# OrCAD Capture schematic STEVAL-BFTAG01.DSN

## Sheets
1 LOGHI
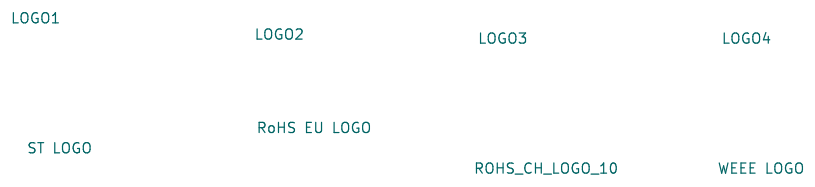
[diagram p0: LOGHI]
2 TOP_sch: size A
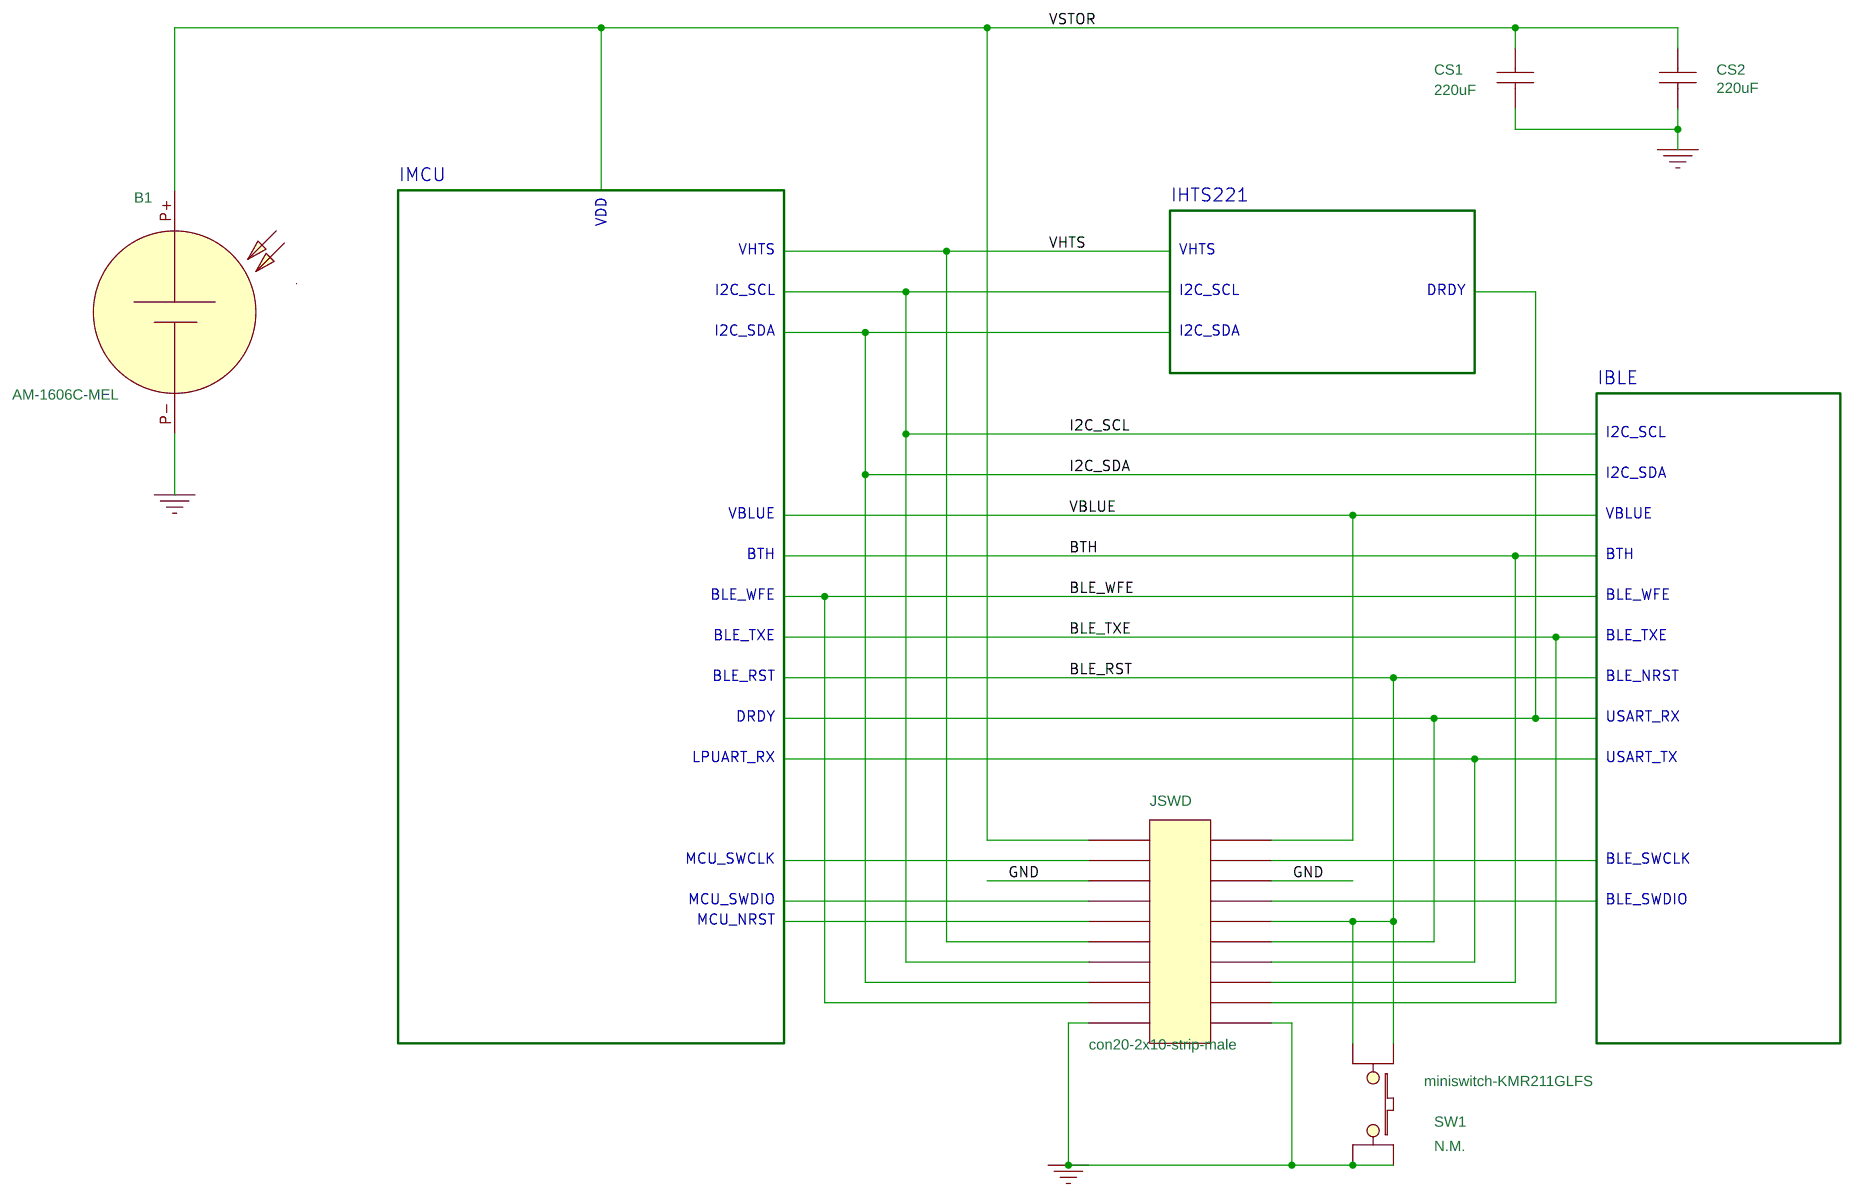
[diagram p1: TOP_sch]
3 MCU_sch: size A; block IMCU
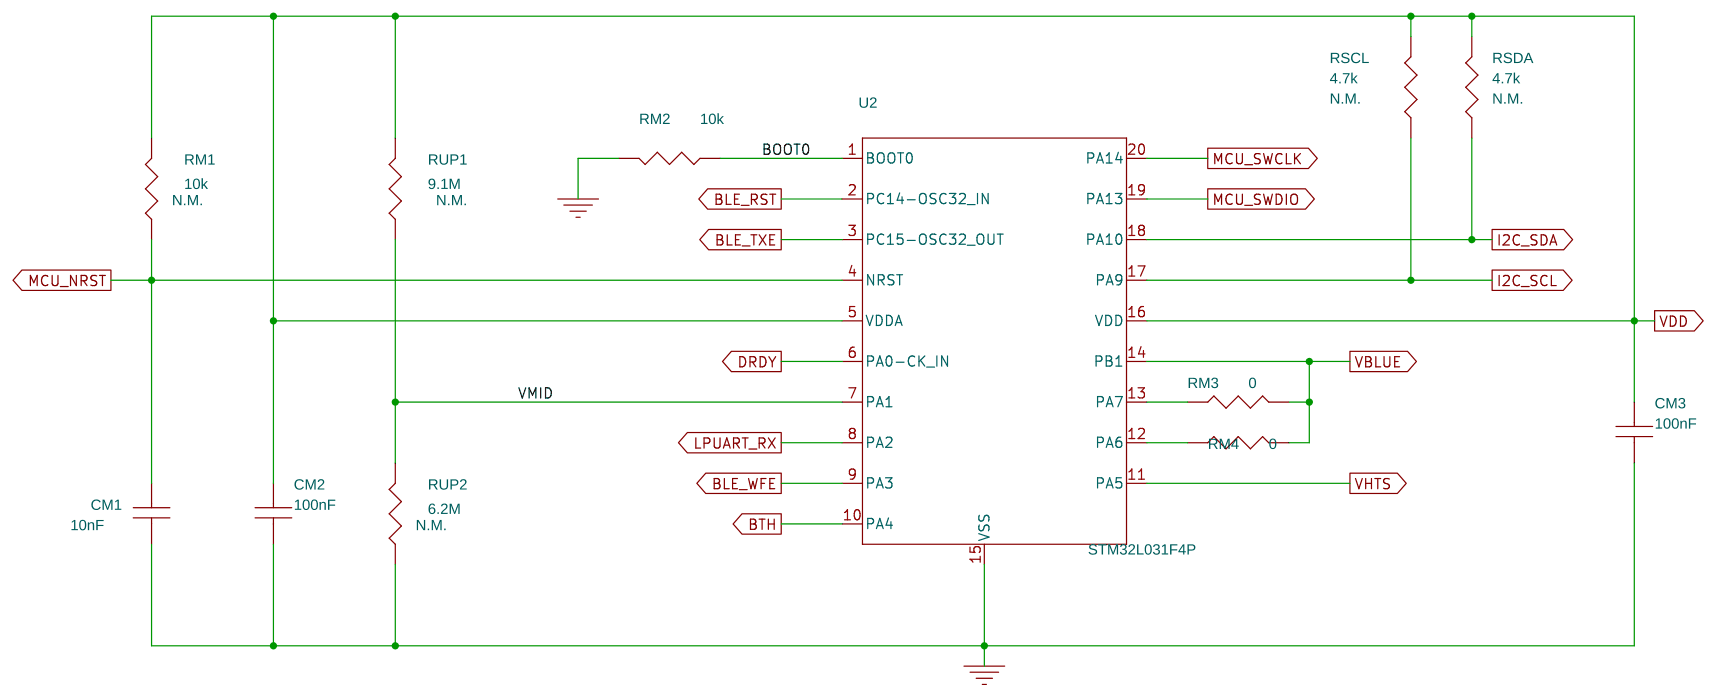
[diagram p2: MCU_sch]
4 BLE_sch: size A; block IBLE
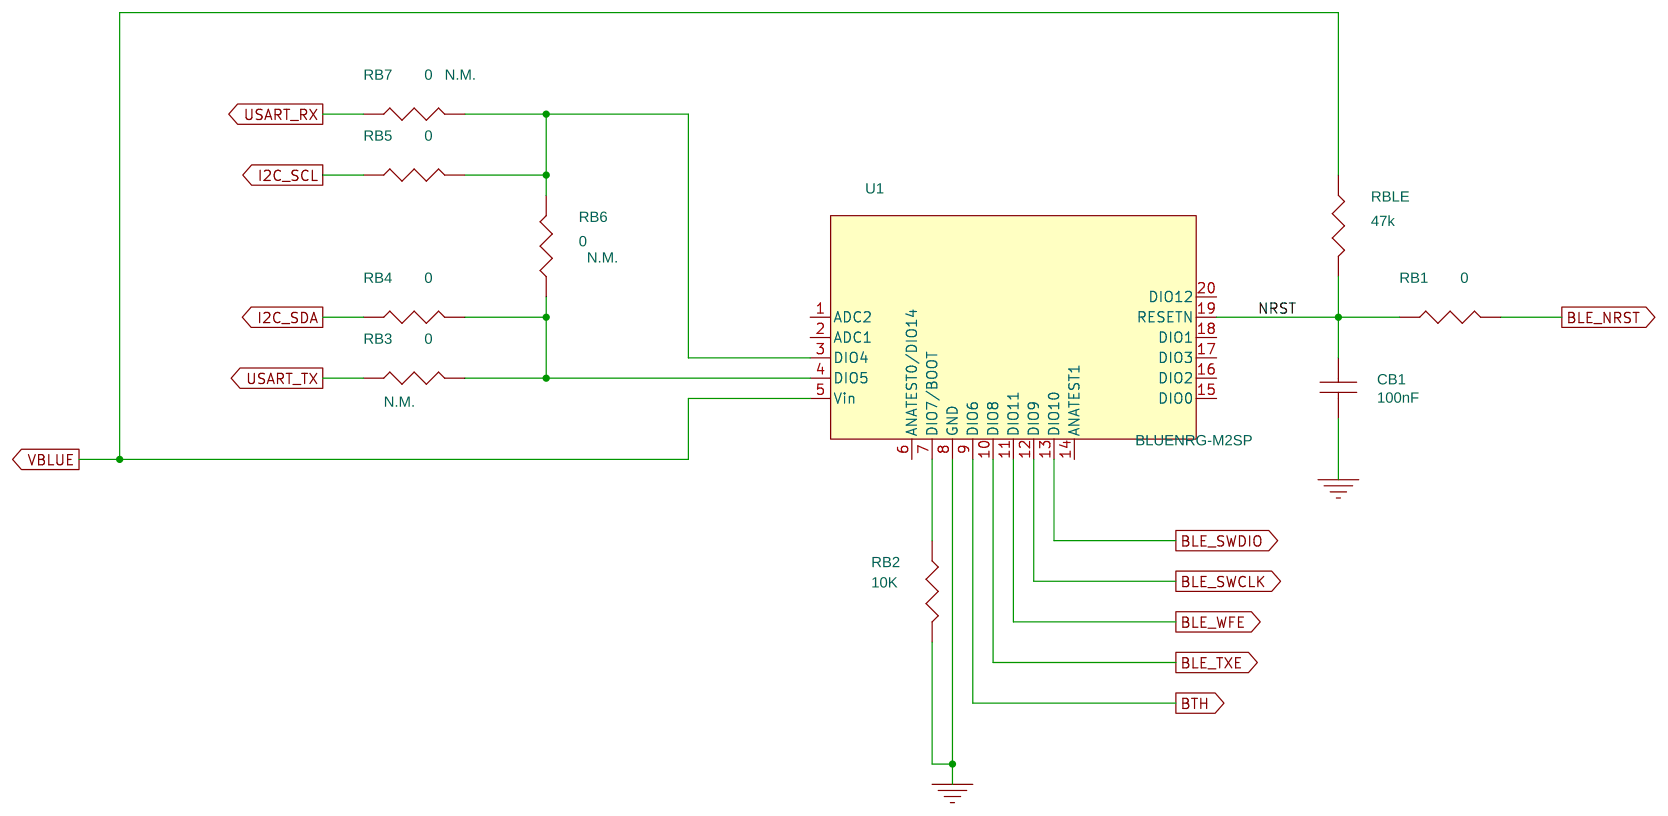
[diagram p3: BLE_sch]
5 HTS221_sch: size A; block IHTS221
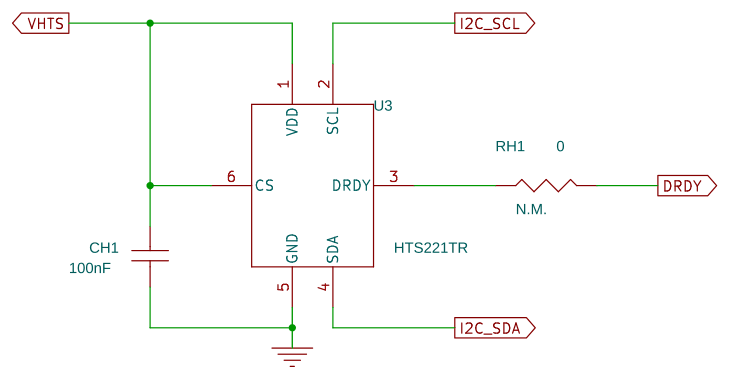
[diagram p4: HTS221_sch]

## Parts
sheet BLE_sch
CB1  100nF  [C_0402]
RB1  0  [r_0402]
RB2  10K  [r_0402]
RB3  0  [r_0402]
RB4  0  [r_0402]
RB5  0  [r_0402]
RB6  0  [r_0402]
RB7  0  [r_0402]
RBLE  47k  [r_0402]
U1  BLUENRG-M2SP  [BLUENRG-M2SP]
sheet HTS221_sch
CH1  100nF  [C_0402]
RH1  0  [r_0402]
U3  HTS221TR  [PQFN100P200X200X100-6N]
sheet LOGHI
LOGO1  ST LOGO  [STLogo12mm]
LOGO2  RoHS EU LOGO  [rohs-eu-logo13mm]
LOGO3  ROHS_CH_LOGO_10  [rohs-ch-10-12mm]
LOGO4  WEEE LOGO  [weee12mm]
sheet MCU_sch
CM1  10nF  [C_0402]
CM2  100nF  [C_0402]
CM3  100nF  [C_0402]
RM1  10k  [r_0402]
RM2  10k  [r_0402]
RM3  0  [r_0402]
RM4  0  [r_0402]
RSCL  4.7k  [r_0402]
RSDA  4.7k  [r_0402]
RUP1  9.1M  [r_0402]
RUP2  6.2M  [r_0402]
U2  STM32L031F4P  [sop20p65_650x640x120l60x24n]
sheet TOP_sch
B1  AM-1606C-MEL  [solar_panel_AM-1606C-MEL]
CS1  220uF  [C_1206_hd]
CS2  220uF  [C_1206_hd]
JSWD  con20-2x10-strip-male  [hdrv20w64p254_10x2_2540x508h838]
SW1  miniswitch-KMR211GLFS  [switch_SMT_4_2x2_8mm]

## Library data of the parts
CB1 CH1 CM1-CM3 = CAP: CAPACITOR CERAMIC SMD 0402; ALT_SYMBOLS: c_0402_hd; Any Equivalent?: YES; CLASS: DISCRETE; Dielectric Type: Capacitors; Manufacturer: ANY; Manufacturer PN: ANY; PART_NUMBER: CAP-00000065; Package Size: 0402 (1005 Metric); Rated Voltage: 10V; Tolerance: ±10%
RB1 RB2 RB4 RB5 RBLE RM2-RM4 = RES: CHIP RESISTOR SMD 5% 1/16W 0402; ALT_SYMBOLS: r_0402_hd; Any Equivalent?: YES; CLASS: DISCRETE; PART_NUMBER: RES-00000105; Package Size: 0402 (1005 Metric); Rated Power: 0.063W, 1/16W; Tolerance: 5%
RB3 RB6 RB7 RH1 RM1 RSCL RSDA RUP1 RUP2 = RES: CHIP RESISTOR SMD 5% 1/16W 0402; ALT_SYMBOLS: r_0402_hd; Any Equivalent?: YES; Assembly Information: N.M.; CLASS: DISCRETE; PART_NUMBER: RES-00000105; Package Size: 0402 (1005 Metric); Rated Power: 0.063W, 1/16W; Tolerance: 5%
U1 = BLUENRG-M2SP: RX TXRX MODULE BT PCB TRC SMD; Any Equivalent?: NO; CLASS: IC; Manufacturer: STMicroelectronics; PART_NUMBER: IC-00000068; Package Size: 20-SMD Module; Rated Power: 7dbm; Supply Voltage: 1.7V ~ 3.6V
U3 = HTS221_0: SENS HUMI/TEMP 2.5V I2C 4.5% SMD; Any Equivalent?: NO; Assembly Information: <Assembly Information>; CLASS: IC; Manufacturer: STMicroelectronics; PART_NUMBER: IC-00000088; Package Size: HLGA_6L2X2X09; Supply Voltage: 1.7 V ~ 3.6 V
LOGO1 = LOGO_ST: ST LOGO - SILKSCREEN; ALT_SYMBOLS: stlogo11mm,STLogo10mm,STLogo9mm,STLogo8mm,STLogo7mm,STLogo6mm,STLogo5mm,stlogo4mm; CLASS: Mechanical; PART_NUMBER: MECH-00000001
LOGO2 = RoHS_EU: RoHS EU - SILKSCREEN; ALT_SYMBOLS: rohs-eu-logo9mm,RoHS-Eu-Logo7mm,RoHS-Eu-Logo5mm; Any Equivalent?: NOT; CLASS: Mechanical; PART_NUMBER: MIS-00000007
LOGO3 = RoHS_CH_10: ROHS CHINA LOGO 10 - SILKSCREEN; ALT_SYMBOLS: rohs-ch-10-10mm,rohs-ch-10-8mm,rohs-ch-10-6mm,rohs-ch-10-5mm,rohs-ch-10-4mm; CLASS: Mechanical; PART_NUMBER: MIS-00000002
LOGO4 = WEEE: WEEE LOGO - SILKSCREEN; ALT_SYMBOLS: weee10mm,weee8mm,weee7mm; CLASS: Mechanical; PART_NUMBER: LOGO-00000001
U2 = STM32L031F4P: IC MCU 32BIT 16KB FLASH 20TSSOP; Any Equivalent?: NO; CLASS: IC; Manufacturer: STMicroelectronics; Manufacturer PN: STM32L031F4P3; PART_NUMBER: IC-00000115; Package Size: 20-TSSOP (0.173", 4.40mm Width); Supply Voltage: 1.8V ~ 3.6V
B1 = SOLAR_PANEL: Solar Panels & Solar Cells Solar BLE Sensor 15x15mm Min 100 Lux; Any Equivalent?: NO; CLASS: DISCRETE; Manufacturer: Panasonic Battery; PART_NUMBER: MIS-00000033
CS1 CS2 = CAP: CAP CER 220UF 4V X6S 1206; Any Equivalent?: NO; CLASS: DISCRETE; Manufacturer: Murata Electronics; Manufacturer PN: GRM31CC80G227ME11L; PART_NUMBER: CAP-00000262; Package Size: 1206 (3216 Metric); Rated Voltage: 4V; Temperature Coefficient: X6S; Tolerance: 20%
JSWD = CON20A: CONN HEADER .100 DUAL STR 20POS; CLASS: IO; PART_NUMBER: CON-00000033
SW1 = PUSHBUTTON-SPST-2: SWITCH TACTILE SPST-NO 0.05A 32V; Assembly Information: N.M.; CLASS: DISCRETE; Manufacturer: C&K; Manufacturer PN: KMR211GLFS; PART_NUMBER: TMP-285; Package Size: 4.60mm x 2.80mm

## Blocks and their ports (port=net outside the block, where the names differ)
IMCU = schematic MCU, on sheet TOP_sch: BLE_RST, VBLUE, MCU_SWCLK=N16953, MCU_SWDIO=N02299, MCU_NRST=N16984, VDD=VSTOR, BLE_WFE, VHTS, BTH, BLE_TXE, I2C_SCL, I2C_SDA, DRDY=N18720, LPUART_RX=N18701
IHTS221 = schematic SENSORS, on sheet TOP_sch: I2C_SDA, DRDY=N18720, VHTS, I2C_SCL
IBLE = schematic BLE, on sheet TOP_sch: VBLUE, BLE_SWDIO=N01742, BLE_SWCLK=N01725, BLE_NRST=BLE_RST, BLE_WFE, BTH, USART_RX=N18720, BLE_TXE, USART_TX=N18701, I2C_SCL, I2C_SDA

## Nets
GND: B1.P- CB1.2 CH1.2 CM1.2 CM2.2 CM3.2 CS1.2 CS2.2 JSWD.5 JSWD.6 JSWD.19 JSWD.20 RB2.2 RM2.2 RUP2.1 SW1.3 SW1.4 U1.8(GND) U2.15(VSS) U3.5(GND)
ANATEST1: U1.14(ANATEST1)
BLE_RST: JSWD.10 RB1.2 SW1.1 SW1.2 U2.2(PC14-OSC32_IN)
BLE_TXE: JSWD.18 U1.10(DIO8) U2.3(PC15-OSC32_OUT)
BLE_WFE: JSWD.17 U1.11(DIO11) U2.9(PA3)
BTH: JSWD.16 U1.9(DIO6) U2.10(PA4)
I2C_SCL: JSWD.13 RB5.1 RSCL.1 U2.17(PA9) U3.2(SCL)
I2C_SDA: JSWD.15 RB4.1 RSDA.1 U2.18(PA10) U3.4(SDA)
IBLE/NRST: CB1.1 RB1.1 RBLE.2 U1.19(RESETN)
IMCU/BOOT0: RM2.1 U2.1(BOOT0)
IMCU/VMID: RUP1.1 RUP2.2 U2.7(PA1)
VBLUE: JSWD.2 RBLE.1 RM3.2 RM4.2 U1.5(Vin) U2.14(PB1)
VHTS: CH1.1 JSWD.11 U2.11(PA5) U3.1(VDD) U3.6(CS)
VSTOR: B1.P+ CM2.1 CM3.1 CS1.1 CS2.1 JSWD.1 RM1.2 RSCL.2 RSDA.2 RUP1.2 U2.5(VDDA) U2.16(VDD)
IBLE/N07126: RB3.2 RB4.2 RB6.1 U1.4(DIO5)
IBLE/N07255: RB2.1 U1.7(DIO7/BOOT)
IBLE/N07625: RB5.2 RB6.2 RB7.2 U1.3(DIO4)
IHTS221/N19245: RH1.1 U3.3(DRDY)
IMCU/N14342: RM4.1 U2.12(PA6)
IMCU/N14407: RM3.1 U2.13(PA7)
N01725: JSWD.4 U1.12(DIO9)
N01742: JSWD.8 U1.13(DIO10)
N02299: JSWD.7 U2.19(PA13)
N16953: JSWD.3 U2.20(PA14)
N16984: CM1.1 JSWD.9 RM1.1 U2.4(NRST)
N18701: JSWD.14 RB3.1 U2.8(PA2)
N18720: JSWD.12 RB7.1 RH1.2 U2.6(PA0-CK_IN)

Not connected (* = marked no-connect by the designer): U1 1(ADC2) 2(ADC1) 6(ANATEST0/DIO14) 15(DIO0) 16(DIO2) 17(DIO3) 18(DIO1) 20(DIO12)
